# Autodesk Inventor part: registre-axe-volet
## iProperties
Author: chr
Created: 2001-06
Part Number: registre-axe-volet
Material: Par défaut
Document SubType Name: Modélisation
Designer: chr
Control State: 0
Master: False
Checked Out: False
PropertySet Name: Design Tracking Control
Shininess: 20.0
PropertySet Name: _Private Model Information
Length Units: 11269
Angle Units: 11286
Time Units: 11279
Mass Units: 11290
Length Display Precision: 3
Angle Display Precision: 2
Compacted: False
Density: 0.0
Volumn: 0.0
Area: 0.0
PropertySet Name: Model Information
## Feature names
1. Extrusion1
2. Extrusion2
3. Extrusion3
4. Extrusion4
5. Extrusion5
6. Réseau circulaire1 [Circular Pattern]
